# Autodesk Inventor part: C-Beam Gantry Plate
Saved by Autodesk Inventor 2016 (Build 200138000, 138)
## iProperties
Created: 2016-01
Part Number: C-Beam Gantry Plate
Material: Generic
Document SubType Name: Modeling
Designer: John
Density: 1 g/cm^3
Appearance: Default
Author: John
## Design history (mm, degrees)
feature "CUT-EXTRUDE1"
body "Solid1"
